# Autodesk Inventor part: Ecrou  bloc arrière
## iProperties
Shininess: 20.0
Angle Display Precision: 2
Document Length Units: 11269
Document Angle Units: 11279
Document Time Units: 11290
Document Mass Units: 11283
Document Length Units Precision: 3
Document Angle Units Precision: 2
Created: 2002-09
Part Number: Ecrou  bloc arrière
Material: Par défaut
Document SubType Name: Modélisation
Designer: administrateur
Density: 0.0
Volumn: 0.0
Area: 0.0
PropertySet Name: Model Information
Control State: 0
Master: False
Checked Out: False
Author: administrateur
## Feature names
1. Base1
